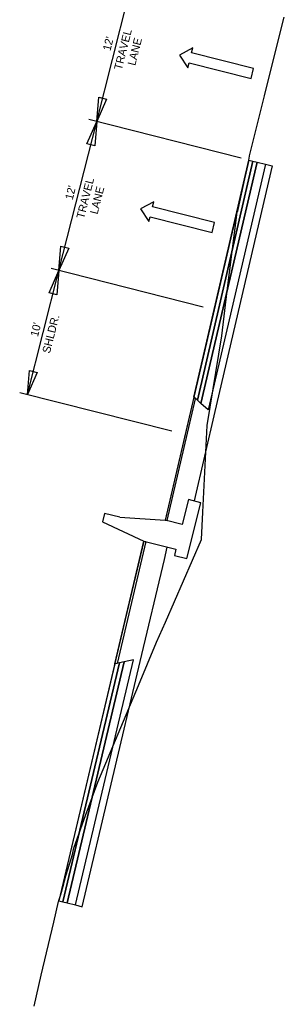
# Model space of a CAD drawing. Extents: x 670006 to 670131, y 737844 to 738002.
# Drawn here: x 670082.2 to 670102.9, y 737843.9 to 737920.9 of the extents above; entities that cross this region are included whole.
import ezdxf

# ---------------------------------------------------------------- set-up
doc = ezdxf.new("R2010")
doc.units = 0
for name, color, linetype in [('R_Alt Surface', 7, 'Continuous'), ('R_Exist Surface', 7, 'Continuous'), ('R_Fin Surface', 7, 'Continuous'), ('R_MOT', 7, 'Continuous'), ('R_SIGN_ANNOT', 7, 'Continuous')]:
    doc.layers.add(name, color=color, linetype=linetype)

msp = doc.modelspace()

# ---------------------------------------------------------------- linework, layer by layer
for points in [[(670091.899, 737880.176), (670094.415, 737879.538), (670094.292, 737879.053), (670095.262, 737878.807), (670096.368, 737883.169), (670095.399, 737883.415), (670094.907, 737881.476), (670093.574, 737881.814)], [(670090.018, 737882.029), (670088.834, 737882.329), (670088.67, 737881.683), (670088.67, 737881.683)], [(670090.018, 737882.029), (670093.574, 737881.814)], [(670088.67, 737881.683), (670091.899, 737880.176)]]:
    msp.add_lwpolyline(points)
at = {"layer": 'R_Alt Surface'}
for points in [[(670101.392, 737909.588), (670101.917, 737909.455), (670097.458, 737890.294), (670095.831, 737883.305)], [(670093.507, 737878.737), (670093.738, 737879.71)], [(670086.556, 737851.764), (670087.081, 737851.631), (670091.619, 737870.771), (670093.507, 737878.737)]]:
    msp.add_lwpolyline(points, dxfattribs=at)
for points in [[(670100.426, 737909.833), (670100.745, 737909.752), (670096.367, 737890.917), (670096.085, 737891.16)], [(670100.745, 737909.752), (670101.392, 737909.588), (670096.934, 737890.427), (670096.367, 737890.917)], [(670085.59, 737852.009), (670085.91, 737851.928), (670090.363, 737870.744), (670089.999, 737870.664)], [(670085.91, 737851.928), (670086.556, 737851.764), (670091.095, 737870.904), (670090.363, 737870.744)]]:
    msp.add_lwpolyline(points, close=True, dxfattribs=at)
at = {"layer": 'R_Exist Surface'}
msp.add_lwpolyline([(670083.337, 737843.857), (670083.899, 737846.283), (670084.868, 737850.414), (670085.253, 737852.033), (670085.27, 737852.09), (670085.279, 737852.126), (670085.424, 737852.595), (670085.663, 737853.411), (670085.717, 737853.648), (670085.815, 737854.028), (670086.097, 737854.959), (670086.328, 737855.711), (670086.448, 737856.23), (670086.456, 737856.273), (670087.347, 737858.749), (670088.317, 737861.339), (670091.489, 737868.9), (670092.906, 737872.275), (670093.595, 737873.833), (670096.405, 737880.285), (670096.505, 737882.425), (670096.844, 737889.192), (670097.987, 737896.204), (670098.418, 737899.712), (670099.157, 737905.634), (670099.195, 737905.865), (670099.234, 737905.922), (670099.261, 737906.044), (670100.056, 737909.636), (670100.104, 737909.905), (670100.106, 737909.914), (670100.16, 737910.218), (670100.163, 737910.235), (670101.325, 737914.929), (670101.41, 737915.266), (670102.87, 737921.083)], dxfattribs=at)
at = {"layer": 'R_Fin Surface'}
for points in [[(670100.106, 737909.914), (670097.388, 737898.223), (670095.124, 737888.481), (670093.574, 737881.814)], [(670091.899, 737880.176), (670090.324, 737873.505), (670088.027, 737863.771), (670085.27, 737852.09)]]:
    msp.add_lwpolyline(points, dxfattribs=at)
for points in [[(670100.106, 737909.914), (670100.426, 737909.833), (670096.085, 737891.16), (670095.803, 737891.404)], [(670095.803, 737891.404), (670093.574, 737881.814), (670093.736, 737881.774), (670095.944, 737891.282)], [(670089.635, 737870.585), (670091.899, 737880.176), (670092.06, 737880.135), (670089.817, 737870.624)], [(670085.27, 737852.09), (670085.59, 737852.009), (670089.999, 737870.664), (670089.635, 737870.585)]]:
    msp.add_lwpolyline(points, close=True, dxfattribs=at)
at = {"layer": 'R_MOT'}
for p, q in [((670095.729, 737918.668), (670094.682, 737918.108)), ((670094.682, 737918.108), (670095.335, 737917.117)), ((670095.63, 737918.28), (670095.729, 737918.668)), ((670100.473, 737917.052), (670095.63, 737918.28)), ((670095.335, 737917.117), (670095.434, 737917.505)), ((670095.434, 737917.505), (670100.276, 737916.276)), ((670100.276, 737916.276), (670100.473, 737917.052)), ((670092.683, 737906.66), (670091.636, 737906.1)), ((670092.585, 737906.272), (670092.683, 737906.66)), ((670091.636, 737906.1), (670092.29, 737905.109)), ((670097.427, 737905.044), (670092.585, 737906.272)), ((670092.29, 737905.109), (670092.388, 737905.497)), ((670092.388, 737905.497), (670097.231, 737904.268)), ((670097.231, 737904.268), (670097.427, 737905.044))]:
    msp.add_line(p, q, dxfattribs=at)
at = {"layer": 'R_SIGN_ANNOT'}
for p, q in [((670088.228, 737912.926), (670091.178, 737924.558)), ((670085.278, 737901.295), (670088.228, 737912.926)), ((670099.5, 737910.068), (670087.622, 737913.08)), ((670082.82, 737891.602), (670085.278, 737901.295)), ((670096.55, 737898.436), (670084.672, 737901.448)), ((670094.091, 737888.743), (670082.214, 737891.755))]:
    msp.add_line(p, q, dxfattribs=at)
for points in [[(670088.992, 737914.667), (670088.228, 737912.926), (670088.386, 737914.821)], [(670087.464, 737911.186), (670088.228, 737912.926), (670088.07, 737911.032)], [(670086.042, 737903.035), (670085.278, 737901.295), (670085.436, 737903.189)], [(670084.514, 737899.554), (670085.278, 737901.295), (670085.12, 737899.4)], [(670083.584, 737893.342), (670082.82, 737891.602), (670082.978, 737893.496)]]:
    msp.add_lwpolyline(points, close=True, dxfattribs=at)

# ---------------------------------------------------------------- texts
for s, p in [('TRAVEL', (670090.177, 737916.901)), ("12'", (670089.294, 737918.399)), ('LANE', (670091.232, 737917.248)), ('TRAVEL', (670087.233, 737905.296)), ("12'", (670086.344, 737906.768)), ('LANE', (670088.288, 737905.643)), ("10'", (670083.633, 737896.081)), ('SHLDR.', (670084.568, 737894.789))]:
    msp.add_text(s, height=0.625, rotation=75.76855, dxfattribs=at).set_placement(p)

doc.saveas('drawing.dxf')
